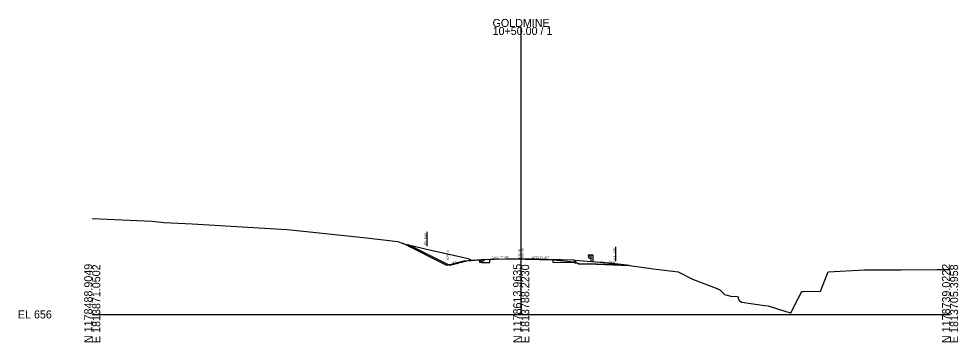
# Model space of a CAD drawing. Extents: x -26 to 1603, y -10 to 1590.
# Drawn here: x 1274.3 to 1602.8, y -9.7 to 103.3 of the extents above; entities that cross this region are included whole.
import ezdxf

# ---------------------------------------------------------------- set-up
doc = ezdxf.new("R2010")
doc.units = 0
for name, color, linetype in [('Default', 7, 'Continuous'), ('RD_EX_RW', 7, 'Continuous'), ('RD_GPK_XS_Cell', 7, 'Continuous'), ('RD_XS_Base', 7, 'Continuous'), ('RD_XS_EarthShd', 7, 'Continuous'), ('RD_XS_ExGround', 7, 'Continuous'), ('RD_XS_GR', 7, 'Continuous'), ('RD_XS_Misc_Line', 7, 'Continuous'), ('RD_XS_Pave', 7, 'Continuous'), ('RD_XS_TieSlope', 7, 'Continuous'), ('RD_XS_TX_Elev_EX', 7, 'Continuous'), ('RD_XS_TX_Elev_PR', 7, 'Continuous'), ('RD_XS_TX_Slope', 7, 'Continuous')]:
    doc.layers.add(name, color=color, linetype=linetype)

msp = doc.modelspace()

# ---------------------------------------------------------------- linework, layer by layer
at = {"layer": 'Default'}
for p, q in [((1450, 19.39), (1436, 19.1)), ((1468.6, 19), (1450, 19.39))]:
    msp.add_line(p, q, dxfattribs=at)
at = {"layer": 'RD_EX_RW'}
for p, q in [((1417, 28.81), (1417, 23.81)), ((1483, 23.62), (1483, 18.62))]:
    msp.add_line(p, q, dxfattribs=at)
at = {"layer": 'RD_GPK_XS_Cell'}
for p, q in [((1450, 0), (1450, 100.41)), ((1300, 0), (1450, 0)), ((1450, 0), (1600, 0))]:
    msp.add_line(p, q, dxfattribs=at)
at = {"layer": 'RD_XS_Base'}
for p, q in [((1436.19, 18.1), (1439.08, 18.16)), ((1439.08, 18.16), (1439.08, 19.31)), ((1461.21, 18.16), (1461.21, 19.08)), ((1468.6, 18), (1461.21, 18.16))]:
    msp.add_line(p, q, dxfattribs=at)
at = {"layer": 'RD_XS_EarthShd'}
for p, q in [((1436, 19.1), (1430, 18.6)), ((1468.6, 19), (1477.6, 18.25))]:
    msp.add_line(p, q, dxfattribs=at)
at = {"layer": 'RD_XS_ExGround'}
msp.add_lwpolyline([(1300, 33.47), (1320.92, 32.57), (1325.12, 32.13), (1334.89, 31.7), (1367.99, 29.66), (1369.35, 29.58), (1394.87, 26.87), (1406.92, 25.49), (1408.61, 24.8), (1417.96, 22.58), (1423.72, 21.3), (1431.49, 19.52), (1432.67, 18.95), (1439.08, 19.31), (1450, 19.39), (1450.37, 19.39), (1450.74, 19.38), (1461.21, 19.08), (1468.51, 18.39), (1470.45, 17.58), (1473.47, 17.73), (1487.93, 17.04), (1496.27, 15.96), (1504.94, 14.9), (1509.93, 12.3), (1518.19, 9.15), (1519.47, 8.55), (1521.16, 6.97), (1523.79, 6.28), (1525.62, 6.4), (1526.19, 4.85), (1527.14, 4.34), (1535.12, 3.11), (1536.38, 2.97), (1542.51, 0.99), (1544.28, 0.59), (1546.83, 5.6), (1548.19, 7.99), (1548.68, 7.99), (1554.72, 8.18), (1557.39, 14.93), (1570.02, 15.62), (1582.9, 15.63), (1595.52, 15.66), (1600, 15.66)], dxfattribs=at)
at = {"layer": 'RD_XS_GR'}
for p, q in [((1473.74, 20.77), (1473.46, 20.57)), ((1473.46, 20.57), (1473.46, 20.52)), ((1473.46, 20.52), (1473.74, 20.32)), ((1473.46, 20), (1473.74, 20.2)), ((1473.46, 19.95), (1473.46, 20)), ((1473.74, 19.75), (1473.46, 19.95)), ((1473.74, 20.85), (1474.4, 20.85)), ((1473.74, 19.68), (1473.74, 20.85)), ((1474.4, 20.85), (1475.07, 20.85)), ((1474.4, 20.85), (1474.4, 18.52)), ((1475.07, 20.85), (1475.07, 18.46)), ((1473.74, 19.68), (1474.4, 19.68))]:
    msp.add_line(p, q, dxfattribs=at)
at = {"layer": 'RD_XS_Misc_Line'}
for points in [[(1437, 19.12), (1431, 18.62), (1425, 17.12), (1410.56, 24.34), (1417.96, 22.58), (1423.72, 21.3), (1431.49, 19.52), (1432.67, 18.95), (1439.08, 19.31), (1439.08, 19.16)], [(1437, 18.12), (1439.08, 18.16), (1439.08, 19.16), (1437, 19.12), (1437, 18.79), (1436.5, 18.78), (1436.5, 18.11)], [(1450, 19.39), (1439.08, 19.16), (1439.08, 19.31)], [(1450, 19.39), (1450.37, 19.39), (1450.74, 19.38), (1451.51, 19.36)], [(1469.1, 18.66), (1468.6, 18.67), (1468.6, 19), (1451.51, 19.36), (1461.21, 19.08), (1468.51, 18.39), (1469.1, 18.14)], [(1461.21, 18.16), (1461.21, 19.08), (1468.51, 18.39), (1469.1, 18.14), (1469.1, 17.99), (1468.6, 18)], [(1468.6, 19), (1477.6, 18.25), (1487.93, 17.04), (1473.47, 17.73), (1470.45, 17.58), (1469.1, 18.14), (1469.1, 18.66), (1468.6, 18.67)]]:
    msp.add_lwpolyline(points, close=True, dxfattribs=at)
at = {"layer": 'RD_XS_Pave'}
for p, q in [((1435.5, 18.76), (1436, 18.77)), ((1435.5, 18.09), (1435.5, 18.76)), ((1436.19, 18.1), (1435.5, 18.09)), ((1436, 18.77), (1436, 19.1)), ((1468.6, 18.67), (1468.6, 19)), ((1469.1, 18.66), (1468.6, 18.67)), ((1468.6, 18), (1469.1, 17.99)), ((1469.1, 17.99), (1469.1, 18.66))]:
    msp.add_line(p, q, dxfattribs=at)
at = {"layer": 'RD_XS_TieSlope'}
for p, q in [((1424, 17.1), (1408.51, 24.84)), ((1430, 18.6), (1424, 17.1)), ((1487.93, 17.04), (1477.6, 18.25))]:
    msp.add_line(p, q, dxfattribs=at)

# ---------------------------------------------------------------- texts
at = {"layer": 'Default'}
msp.add_text(' 675.39', height=0.8, rotation=90, dxfattribs=at).set_placement((1450.91, 19.39))
at = {"layer": 'RD_EX_RW'}
for p in [(1416.94, 24.34), (1482.94, 19.14)]:
    msp.add_text('EX. R/W', height=0.75, rotation=90, dxfattribs=at).set_placement(p)
at = {"layer": 'RD_GPK_XS_Cell'}
for s, p in [('GOLDMINE', (1440, 100.41)), ('10+50.00 / 1', (1440, 97.61)), ('EL 656', (1274, -1.4))]:
    msp.add_text(s, height=2.8, dxfattribs=at).set_placement(p)
for s, p in [('N 1178488.9049', (1300, -10)), ('E 1813871.0502', (1302.8, -10)), ('N 1178613.9635', (1450, -10)), ('E 1813788.2230', (1452.8, -10)), ('N 1178739.0222', (1600, -10)), ('E 1813705.3958', (1602.8, -10))]:
    msp.add_text(s, height=2.8, rotation=90, dxfattribs=at).set_placement(p)
at = {"layer": 'RD_XS_TX_Elev_EX'}
msp.add_text('675.39', height=0.8, rotation=90, dxfattribs=at).set_placement((1449.92, 19.55))
at = {"layer": 'RD_XS_TX_Elev_PR'}
msp.add_text('673.10', height=0.8, rotation=90, dxfattribs=at).set_placement((1424.8, 19.1))
at = {"layer": 'RD_XS_TX_Slope'}
for s, rotation, p in [('0.021 FT./FT.', 1.1916, (1439.71, 19.43)), ('0.021 FT./FT.', 358.8084, (1453.72, 19.56)), ('4:1', 14.0362, (1426.11, 17.75)), ('VAR.', 353.1002, (1480.69, 17.97))]:
    msp.add_text(s, height=0.75, rotation=rotation, dxfattribs=at).set_placement(p)

doc.saveas('drawing.dxf')
